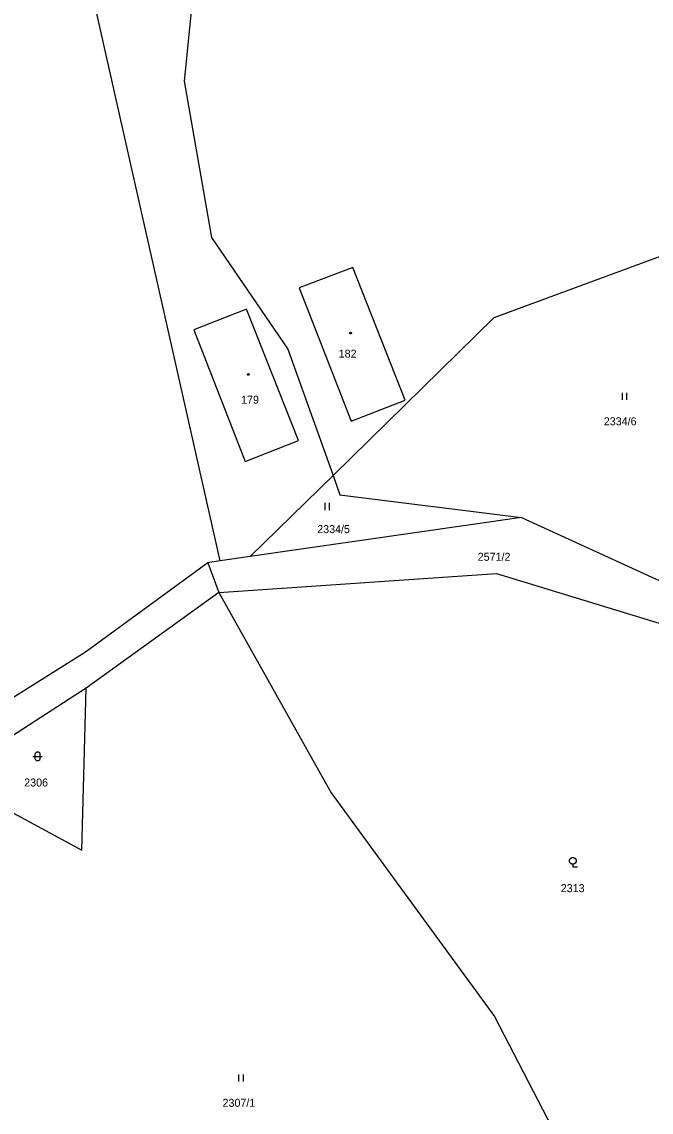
# Model space of a CAD drawing. Extents: x -747792 to -745414, y -1093712 to -1091463.
# Drawn here: x -746752.4 to -746685.5, y -1092966.2 to -1092850.4 of the extents above; entities that cross this region are included whole.
import ezdxf

# ---------------------------------------------------------------- set-up
doc = ezdxf.new("R2010")
doc.units = 0
for name, color, linetype in [('Pracovní_bod JDTM STC_VC', 7, 'Continuous'), ('Pracovní_bod JDTM STC_VC - výška', 7, 'Continuous'), ('Pracovní_bod JDTM STC_VC - číslo', 7, 'Continuous'), ('Pracovní_bod NN - výška', 7, 'Continuous')]:
    doc.layers.add(name, color=color, linetype=linetype)

msp = doc.modelspace()

# ---------------------------------------------------------------- linework, layer by layer
at = {"layer": 'Pracovní_bod JDTM STC_VC - výška'}
for points in [[(-746717.44, -1092883.4), (-746717.39, -1092883.41), (-746717.36, -1092883.45), (-746717.35, -1092883.48), (-746717.36, -1092883.52), (-746717.41, -1092883.56), (-746717.44, -1092883.56), (-746717.48, -1092883.55), (-746717.51, -1092883.52), (-746717.52, -1092883.48), (-746717.51, -1092883.44), (-746717.47, -1092883.4)], [(-746728.3, -1092887.79), (-746728.25, -1092887.8), (-746728.23, -1092887.85), (-746728.22, -1092887.88), (-746728.23, -1092887.92), (-746728.27, -1092887.96), (-746728.3, -1092887.96), (-746728.34, -1092887.95), (-746728.38, -1092887.92), (-746728.39, -1092887.88), (-746728.38, -1092887.83), (-746728.33, -1092887.8)]]:
    msp.add_lwpolyline(points, close=True, dxfattribs=at)
at = {"layer": 'Pracovní_bod JDTM STC_VC - číslo'}
for points in [[(-746688.62, -1092889.83), (-746688.62, -1092890.58)], [(-746688.12, -1092890.58), (-746688.12, -1092889.83)], [(-746720.18, -1092901.53), (-746720.18, -1092902.28)], [(-746719.68, -1092902.28), (-746719.68, -1092901.53)], [(-746751.18, -1092928.44), (-746750.55, -1092928.44), (-746750.18, -1092928.44)], [(-746693.86, -1092939.9), (-746693.95, -1092939.9), (-746694.12, -1092939.8), (-746694.22, -1092939.63), (-746694.22, -1092939.44), (-746694.12, -1092939.27), (-746693.95, -1092939.17), (-746693.76, -1092939.17), (-746693.59, -1092939.27), (-746693.49, -1092939.44), (-746693.49, -1092939.63), (-746693.59, -1092939.8), (-746693.76, -1092939.9), (-746693.85, -1092939.9), (-746693.85, -1092940.16), (-746693.35, -1092940.16)], [(-746729.33, -1092962.21), (-746729.33, -1092962.96)], [(-746728.83, -1092962.96), (-746728.83, -1092962.21)]]:
    msp.add_lwpolyline(points, dxfattribs=at)
msp.add_lwpolyline([(-746750.93, -1092928.19), (-746750.88, -1092928.04), (-746750.76, -1092927.96), (-746750.6, -1092927.96), (-746750.48, -1092928.04), (-746750.43, -1092928.19), (-746750.43, -1092928.69), (-746750.48, -1092928.83), (-746750.6, -1092928.92), (-746750.76, -1092928.92), (-746750.88, -1092928.83), (-746750.93, -1092928.69)], close=True, dxfattribs=at)
at = {"layer": 'Pracovní_bod NN - výška'}
for points in [[(-746731.28, -1092907.69), (-746745.88, -1092842.91)], [(-746733.89, -1092844.34), (-746735.11, -1092856.73)], [(-746735.11, -1092856.73), (-746732.21, -1092873.33)], [(-746702.19, -1092881.84), (-746673.9, -1092871.4)], [(-746732.21, -1092873.33), (-746724.1, -1092885.21)], [(-746719.31, -1092898.61), (-746702.19, -1092881.84)], [(-746724.1, -1092885.21), (-746719.31, -1092898.61)], [(-746728.11, -1092907.23), (-746719.31, -1092898.61)], [(-746719.31, -1092898.61), (-746718.58, -1092900.66)], [(-746718.58, -1092900.66), (-746699.3, -1092903.07)], [(-746699.3, -1092903.07), (-746728.11, -1092907.23)], [(-746699.3, -1092903.07), (-746674.17, -1092914.57)], [(-746732.62, -1092907.88), (-746745.58, -1092917.36)], [(-746731.28, -1092907.69), (-746732.62, -1092907.88)], [(-746732.62, -1092907.88), (-746731.42, -1092911.03)], [(-746728.11, -1092907.23), (-746731.28, -1092907.69)], [(-746731.42, -1092911.03), (-746701.96, -1092909.01)], [(-746701.96, -1092909.01), (-746676.22, -1092916.88)], [(-746731.42, -1092911.03), (-746745.53, -1092921.19)], [(-746731.42, -1092911.03), (-746719.5, -1092932.33)], [(-746745.58, -1092917.36), (-746760.87, -1092926.96)], [(-746745.53, -1092921.19), (-746758.3, -1092929.43)], [(-746745.98, -1092938.41), (-746745.53, -1092921.19)], [(-746760.93, -1092930.34), (-746745.98, -1092938.41)], [(-746719.5, -1092932.33), (-746702.15, -1092956.05)], [(-746702.15, -1092956.05), (-746689.35, -1092980.81)]]:
    msp.add_lwpolyline(points, dxfattribs=at)
for points in [[(-746722.89, -1092878.68), (-746717.38, -1092892.83), (-746711.66, -1092890.62), (-746717.21, -1092876.51)], [(-746734.09, -1092883.14), (-746728.64, -1092897.11), (-746722.99, -1092894.91), (-746728.5, -1092880.94)]]:
    msp.add_lwpolyline(points, close=True, dxfattribs=at)

# ---------------------------------------------------------------- texts
at = {"layer": 'Pracovní_bod JDTM STC_VC'}
for s, p in [('182', (-746718.71, -1092886.1)), ('179', (-746729.07, -1092890.99)), ('2334/6', (-746690.56, -1092893.28)), ('2334/5', (-746720.99, -1092904.73)), ('2571/2', (-746703.95, -1092907.67)), ('2306', (-746752.1, -1092931.64)), ('2313', (-746695.13, -1092942.86)), ('2307/1', (-746731.04, -1092965.66))]:
    msp.add_text(s, height=0.85, dxfattribs=at).set_placement(p)

doc.saveas('drawing.dxf')
